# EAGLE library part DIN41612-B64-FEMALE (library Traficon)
Manufacturer: Pancon Angled 90°: CNDIN064F2 Product number: 100-064-533 Straight: CNDIN064F1-1 DIN41612/B Straight-Female 09 02 264 6824
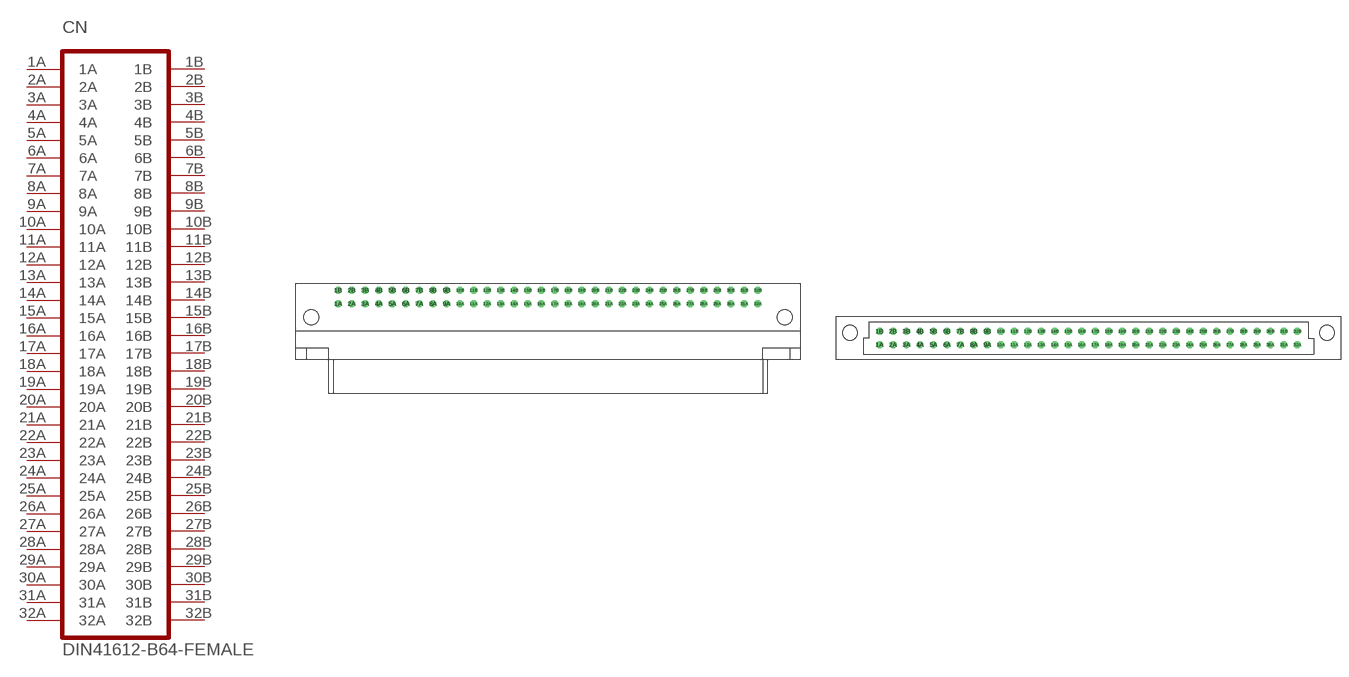
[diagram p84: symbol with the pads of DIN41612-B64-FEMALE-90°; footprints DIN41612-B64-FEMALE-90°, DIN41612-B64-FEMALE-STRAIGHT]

Designator prefix CN

## DIN41612-B64-FEMALE-90°  [DIN41612-B64-FEMALE-90°]
1A  1A
1B  1B
2A  2A
2B  2B
3A  3A
3B  3B
4A  4A
4B  4B
5A  5A
5B  5B
6A  6A
6B  6B
7A  7A
7B  7B
8A  8A
8B  8B
9A  9A
9B  9B
10A  10A
10B  10B
11A  11A
11B  11B
12A  12A
12B  12B
13A  13A
13B  13B
14A  14A
14B  14B
15A  15A
15B  15B
16A  16A
16B  16B
17A  17A
17B  17B
18A  18A
18B  18B
19A  19A
19B  19B
20A  20A
20B  20B
21A  21A
21B  21B
22A  22A
22B  22B
23A  23A
23B  23B
24A  24A
24B  24B
25A  25A
25B  25B
26A  26A
26B  26B
27A  27A
27B  27B
28A  28A
28B  28B
29A  29A
29B  29B
30A  30A
30B  30B
31A  31A
31B  31B
32A  32A
32B  32B

## DIN41612-B64-FEMALE-STRAIGHT  [DIN41612-B64-FEMALE-STRAIGHT]
Pads as for DIN41612-B64-FEMALE-90°

## Footprint DIN41612-B64-FEMALE-90° (pad centres in mm)
drill 0.8 octagon: 1A -40.64,6.35; 1B -40.64,8.89; 2A -38.1,6.35; 2B -38.1,8.89; 3A -35.56,6.35; 3B -35.56,8.89; 4A -33.02,6.35; 4B -33.02,8.89; 5A -30.48,6.35; 5B -30.48,8.89; 6A -27.94,6.35; 6B -27.94,8.89; 7A -25.4,6.35; 7B -25.4,8.89; 8A -22.86,6.35; 8B -22.86,8.89; 9A -20.32,6.35; 9B -20.32,8.89; 10A -17.78,6.35; 10B -17.78,8.89; 11A -15.24,6.35; 11B -15.24,8.89; 12A -12.7,6.35; 12B -12.7,8.89; 13A -10.16,6.35; 13B -10.16,8.89; 14A -7.62,6.35; 14B -7.62,8.89; 15A -5.08,6.35; 15B -5.08,8.89; 16A -2.54,6.35; 16B -2.54,8.89; 17A 0,6.35; 17B 0,8.89; 18A 2.54,6.35; 18B 2.54,8.89; 19A 5.08,6.35; 19B 5.08,8.89; 20A 7.62,6.35; 20B 7.62,8.89; 21A 10.16,6.35; 21B 10.16,8.89; 22A 12.7,6.35; 22B 12.7,8.89; 23A 15.24,6.35; 23B 15.24,8.89; 24A 17.78,6.35; 24B 17.78,8.89; 25A 20.32,6.35; 25B 20.32,8.89; 26A 22.86,6.35; 26B 22.86,8.89; 27A 25.4,6.35; 27B 25.4,8.89; 28A 27.94,6.35; 28B 27.94,8.89; 29A 30.48,6.35; 29B 30.48,8.89; 30A 33.02,6.35; 30B 33.02,8.89; 31A 35.56,6.35; 31B 35.56,8.89; 32A 38.1,6.35; 32B 38.1,8.89
hole 2.8 at 43.18,3.81
hole 2.8 at -45.72,3.81

## Footprint DIN41612-B64-FEMALE-STRAIGHT (pad centres in mm)
drill 0.8 octagon: 1A -38.1,-1.27; 1B -38.1,1.27; 2A -35.56,-1.27; 2B -35.56,1.27; 3A -33.02,-1.27; 3B -33.02,1.27; 4A -30.48,-1.27; 4B -30.48,1.27; 5A -27.94,-1.27; 5B -27.94,1.27; 6A -25.4,-1.27; 6B -25.4,1.27; 7A -22.86,-1.27; 7B -22.86,1.27; 8A -20.32,-1.27; 8B -20.32,1.27; 9A -17.78,-1.27; 9B -17.78,1.27; 10A -15.24,-1.27; 10B -15.24,1.27; 11A -12.7,-1.27; 11B -12.7,1.27; 12A -10.16,-1.27; 12B -10.16,1.27; 13A -7.62,-1.27; 13B -7.62,1.27; 14A -5.08,-1.27; 14B -5.08,1.27; 15A -2.54,-1.27; 15B -2.54,1.27; 16A 0,-1.27; 16B 0,1.27; 17A 2.54,-1.27; 17B 2.54,1.27; 18A 5.08,-1.27; 18B 5.08,1.27; 19A 7.62,-1.27; 19B 7.62,1.27; 20A 10.16,-1.27; 20B 10.16,1.27; 21A 12.7,-1.27; 21B 12.7,1.27; 22A 15.24,-1.27; 22B 15.24,1.27; 23A 17.78,-1.27; 23B 17.78,1.27; 24A 20.32,-1.27; 24B 20.32,1.27; 25A 22.86,-1.27; 25B 22.86,1.27; 26A 25.4,-1.27; 26B 25.4,1.27; 27A 27.94,-1.27; 27B 27.94,1.27; 28A 30.48,-1.27; 28B 30.48,1.27; 29A 33.02,-1.27; 29B 33.02,1.27; 30A 35.56,-1.27; 30B 35.56,1.27; 31A 38.1,-1.27; 31B 38.1,1.27; 32A 40.64,-1.27; 32B 40.64,1.27
hole 2.8 at 46.228,1.016
hole 2.8 at -43.688,1.016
